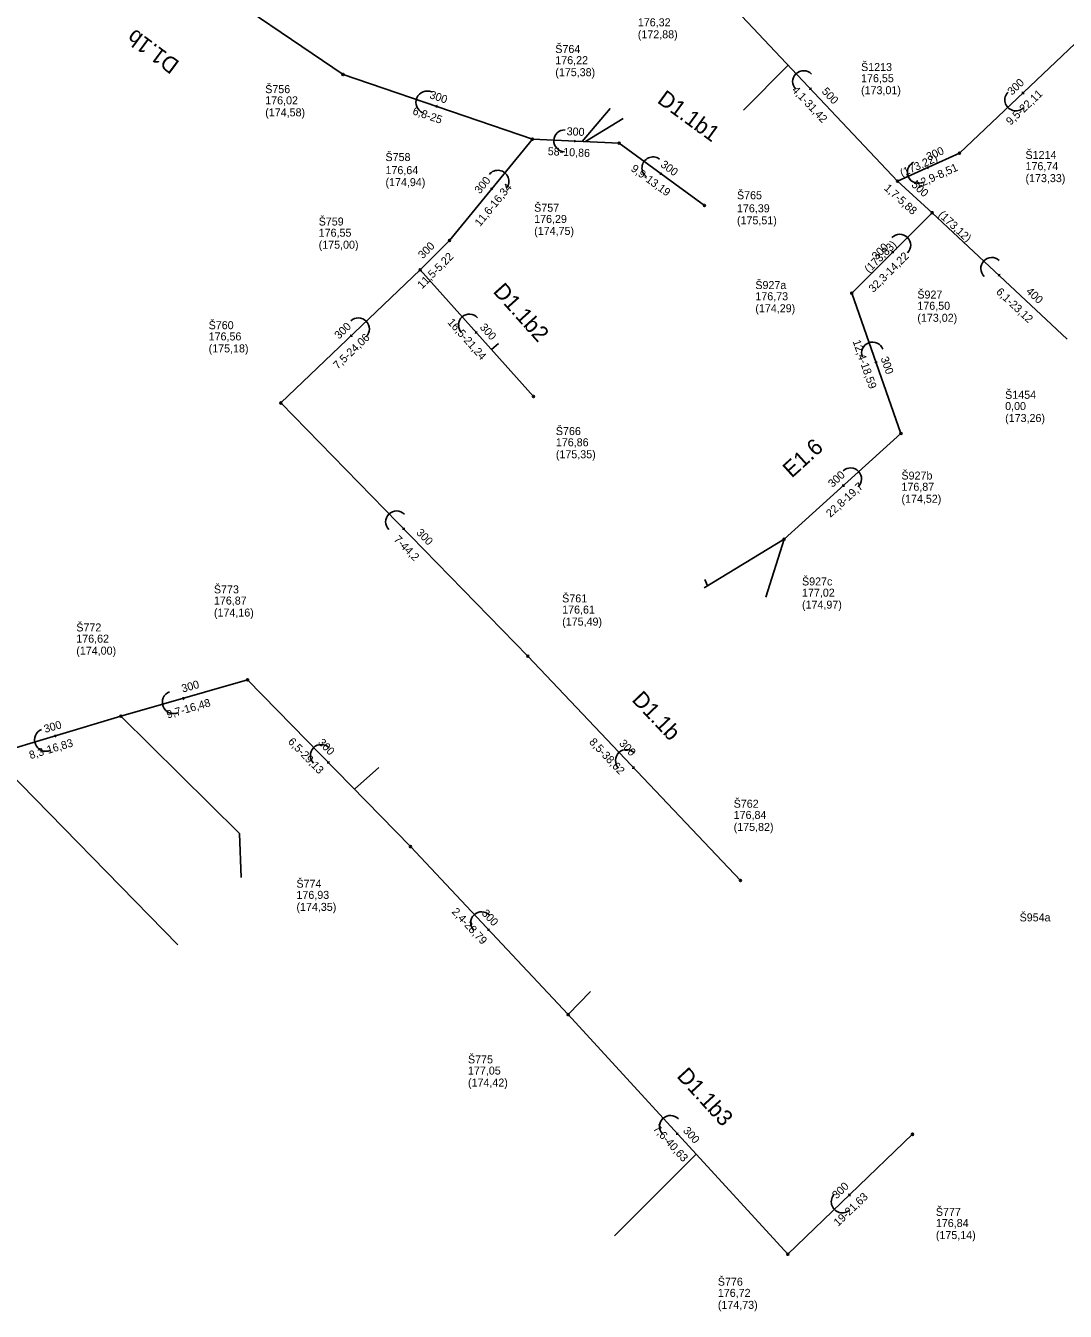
# Model space of a CAD drawing. Extents: x -548529 to -543591, y -1201432 to -1192608.
# Drawn here: x -544814 to -544684, y -1193635.3 to -1193474.6 of the extents above; entities that cross this region are included whole.
import ezdxf

# ---------------------------------------------------------------- set-up
doc = ezdxf.new("R2010")
doc.units = 0
for name, color, linetype in [('C3D_Bod-Značky', 7, 'Continuous'), ('C3D_Koridor', 7, 'Continuous'), ('C3D_Křižovatka', 7, 'Continuous'), ('C3D_Netisknutelná', 7, 'Continuous'), ('C3D_PP-zobrazeni v PR', 7, 'Continuous'), ('C3D_PR-Popisek', 7, 'Continuous'), ('C3D_SPR-Popisek', 7, 'Continuous'), ('C3D_Tlakove_potrubi_Popis', 7, 'Continuous'), ('C3D_ZPR-Formaty', 7, 'Continuous')]:
    doc.layers.add(name, color=color, linetype=linetype)

# ---------------------------------------------------------------- blocks, each defined once
blk = doc.blocks.new('100')
at = {"layer": 'Defpoints'}
blk.add_circle((0, 0), 0.127, dxfattribs=at)
blk = doc.blocks.new('91')
at = {"layer": 'Defpoints'}
blk.add_lwpolyline([(0.08, 0.14), (0.19, 0), (0.08, -0.14)], dxfattribs=at)
blk.add_arc((1.37, 0), 1.37, 270, 90, dxfattribs=at)
blk = doc.blocks.new('86')
at = {"layer": 'Defpoints'}
blk.add_lwpolyline([(0.08, 0.14), (0.19, 0), (0.08, -0.14)], dxfattribs=at)
blk.add_arc((1.37, 0), 1.37, 270, 90, dxfattribs=at)

msp = doc.modelspace()

# ---------------------------------------------------------------- linework, layer by layer
at = {"layer": 'C3D_Bod-Značky'}
for points in [[(-544774.31, -1193480.71), (-544792.51, -1193468.335), (-544810.71, -1193455.96)], [(-544705.03, -1193494.03), (-544726.568, -1193471.155)], [(-544681.22, -1193475.33), (-544697.27, -1193490.54)], [(-544750.65, -1193488.79), (-544774.31, -1193480.71)], [(-544760.99, -1193501.44), (-544750.65, -1193488.79)], [(-544739.8, -1193489.3), (-544750.65, -1193488.79)], [(-544729.145, -1193497.07), (-544739.8, -1193489.3)], [(-544697.27, -1193490.54), (-544705.03, -1193494.03)], [(-544700.674, -1193497.981), (-544705.03, -1193494.03)], [(-544710.739, -1193508.032), (-544700.674, -1193497.981)], [(-544683.794, -1193513.78), (-544700.674, -1193497.981)], [(-544764.68, -1193505.13), (-544760.99, -1193501.44)], [(-544782.07, -1193521.76), (-544764.68, -1193505.13)], [(-544750.51, -1193520.95), (-544764.68, -1193505.13)], [(-544704.58, -1193525.57), (-544710.739, -1193508.032)], [(-544751.22, -1193553.41), (-544782.07, -1193521.76)], [(-544719.18, -1193538.79), (-544704.58, -1193525.57)], [(-544724.65, -1193581.44), (-544751.22, -1193553.41)], [(-544786.23, -1193556.36), (-544802.07, -1193560.9)], [(-544765.878, -1193577.201), (-544786.23, -1193556.36)], [(-544802.07, -1193560.9), (-544818.19, -1193565.74)], [(-544746.181, -1193598.197), (-544765.878, -1193577.201)], [(-544718.728, -1193628.149), (-544746.181, -1193598.197)], [(-544703.141, -1193613.154), (-544718.728, -1193628.149)]]:
    msp.add_lwpolyline(points, dxfattribs=at)
at = {"layer": 'C3D_Koridor'}
for points in [[(-544718.694, -1193479.522), (-544724.269, -1193485.159)], [(-544744.415, -1193489.083), (-544740.938, -1193484.975)], [(-544744.005, -1193489.102), (-544739.285, -1193486.22)], [(-544755.759, -1193515.09), (-544754.866, -1193514.326)], [(-544719.18, -1193538.79), (-544729.157, -1193544.869)], [(-544719.18, -1193538.79), (-544721.481, -1193546.024)], [(-544728.744, -1193544.606), (-544729.096, -1193543.833)], [(-544802.07, -1193560.9), (-544787.248, -1193575.568), (-544787.049, -1193581.052)], [(-544818.19, -1193565.74), (-544794.95, -1193589.492)], [(-544772.88, -1193570.03), (-544769.826, -1193567.304)], [(-544746.181, -1193598.197), (-544743.389, -1193595.317)], [(-544730.184, -1193615.651), (-544740.37, -1193625.847)]]:
    msp.add_lwpolyline(points, dxfattribs=at)

# ---------------------------------------------------------------- block references
at = {"layer": 'C3D_PP-zobrazeni v PR'}
for p, xscale, yscale, rotation in [((-544774.31, -1193480.71), 1.0138865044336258, 1.0138865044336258, 152.43468640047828), ((-544750.65, -1193488.79), 0.9999999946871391, 0.9999999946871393, -73.99999975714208), ((-544739.8, -1193489.3), 1.0316957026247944, 1.0316957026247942, 156.4154111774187), ((-544697.27, -1193490.54), 0.9999999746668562, 0.999999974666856, -145.99999954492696), ((-544705.03, -1193494.03), 1.0000000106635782, 1.0000000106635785, 135.99999834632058), ((-544729.145, -1193497.07), 1.000000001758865, 1.000000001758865, -35.99999933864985), ((-544700.674, -1193497.981), 1.00000001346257, 1.0000000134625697, -178.0000000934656), ((-544760.99, -1193501.44), 1.0000000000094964, 1.0000000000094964, -132.0000013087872), ((-544764.68, -1193505.13), 1.000000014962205, 1.0000000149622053, 89.0000000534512), ((-544710.739, -1193508.032), 1.0000000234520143, 1.0000000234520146, 78.0000006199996), ((-544750.51, -1193520.95), 1.0000000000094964, 1.0000000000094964, -47.99999869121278), ((-544782.07, -1193521.76), 1.000000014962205, 1.0000000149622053, 89.0000000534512), ((-544704.58, -1193525.57), 1.0000000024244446, 1.0000000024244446, -104.00000032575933), ((-544719.18, -1193538.79), 1.00000000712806, 1.00000000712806, 43.0000005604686), ((-544751.22, -1193553.41), 1.0000000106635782, 1.0000000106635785, 134.00000165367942), ((-544786.23, -1193556.36), 1.0009848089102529, 1.000984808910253, 165.77567372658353), ((-544802.07, -1193560.9), 1.035124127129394, 1.0351241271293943, -157.49634583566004), ((-544765.878, -1193577.201), 1.0000000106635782, 1.0000000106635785, 134.00000165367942), ((-544724.65, -1193581.44), 1.0000000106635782, 1.0000000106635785, -45.99999834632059), ((-544746.181, -1193598.197), 1.00000000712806, 1.00000000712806, 133.00000056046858), ((-544703.141, -1193613.154), 1.0000000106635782, 1.0000000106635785, 44.00000165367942), ((-544718.728, -1193628.149), 1.000000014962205, 1.0000000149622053, 179.0000000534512)]:
    msp.add_blockref('100', p, dxfattribs=dict(at, xscale=xscale, yscale=yscale, rotation=rotation))
at = {"layer": 'C3D_SPR-Popisek'}
for name, p, xscale, yscale, rotation in [('91', (-544715.799, -1193482.592), 1.0000000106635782, 1.0000000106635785, 134.00000165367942), ('91', (-544762.48, -1193484.75), 1.033506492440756, 1.033506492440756, 156.95871826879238), ('91', (-544689.245, -1193482.935), 1.0000000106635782, 1.0000000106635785, -135.99999834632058), ('91', (-544745.225, -1193489.045), 1.00000001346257, 1.0000000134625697, 178.0000000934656), ('91', (-544734.472, -1193493.185), 1.000000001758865, 1.000000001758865, 144.00000066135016), ('91', (-544755.82, -1193495.115), 1.000000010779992, 1.0000000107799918, 51.00000108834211), ('91', (-544701.15, -1193492.285), 1.0169562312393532, 1.016956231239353, -153.02398354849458), ('91', (-544705.706, -1193503.006), 0.999999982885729, 0.9999999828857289, 45), ('91', (-544692.234, -1193505.88), 1.00000000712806, 1.00000000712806, 136.99999943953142), ('86', (-544757.595, -1193513.04), 1.0000000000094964, 1.0000000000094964, 132.0000013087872), ('86', (-544773.375, -1193513.445), 1.0000000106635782, 1.0000000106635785, 44.00000165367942), ('91', (-544707.66, -1193516.801), 0.9999999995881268, 0.9999999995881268, 110.00000065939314), ('91', (-544711.88, -1193532.18), 1.00000000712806, 1.00000000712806, 43.0000005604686), ('86', (-544766.645, -1193537.585), 0.999999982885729, 0.9999999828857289, 135), ('86', (-544794.15, -1193558.63), 1.0365458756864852, 1.0365458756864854, -158.02850914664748), ('86', (-544810.13, -1193563.32), 1.035124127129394, 1.0351241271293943, -157.49634583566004), ('86', (-544776.054, -1193566.78), 0.999999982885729, 0.9999999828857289, 135), ('86', (-544737.935, -1193567.425), 1.0000000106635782, 1.0000000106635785, 134.00000165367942), ('86', (-544756.03, -1193587.699), 1.0000000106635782, 1.0000000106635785, 134.00000165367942), ('86', (-544732.454, -1193613.173), 1.00000000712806, 1.00000000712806, 133.00000056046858), ('86', (-544710.934, -1193620.652), 1.0000000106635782, 1.0000000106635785, -135.99999834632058)]:
    msp.add_blockref(name, p, dxfattribs=dict(at, xscale=xscale, yscale=yscale, rotation=rotation))

# ---------------------------------------------------------------- texts
at = {"layer": 'C3D_Křižovatka'}
for s, p in [('Š764', (-544747.78, -1193478.02)), ('Š1213', (-544709.57, -1193480.27)), ('Š756', (-544784.03, -1193483.04)), ('Š758', (-544769, -1193491.53)), ('Š1214', (-544689.02, -1193491.26)), ('Š765', (-544725.075, -1193496.3)), ('Š757', (-544750.42, -1193497.86)), ('Š759', (-544777.35, -1193499.58)), ('Š927a', (-544722.779, -1193507.522)), ('Š927', (-544702.534, -1193508.711)), ('Š760', (-544791.1, -1193512.54)), ('Š1454', (-544691.564, -1193521.24)), ('Š766', (-544747.71, -1193525.77)), ('Š927b', (-544704.52, -1193531.33)), ('Š927c', (-544716.95, -1193544.56)), ('Š773', (-544790.44, -1193545.55)), ('Š761', (-544746.92, -1193546.68)), ('Š772', (-544807.64, -1193550.31)), ('Š762', (-544725.49, -1193572.34)), ('Š774', (-544780.128, -1193582.331)), ('Š954a', (-544689.755, -1193586.547)), ('Š775', (-544758.691, -1193604.287)), ('Š777', (-544700.221, -1193623.344)), ('Š776', (-544727.468, -1193632.069))]:
    msp.add_text(s, height=1, dxfattribs=at).set_placement(p)
at = {"layer": 'C3D_Netisknutelná'}
for s, rotation, p in [('D1.1b', 143.46, (-544794.62, -1193479.169)), ('D1.1b1', 323.9, (-544735.16, -1193484.145)), ('D1.1b2', 311.85, (-544755.655, -1193507.874)), ('E1.6', 42.16, (-544718.233, -1193531.212)), ('D1.1b', 313.47, (-544738.319, -1193558.931)), ('D1.1b3', 312.51, (-544732.698, -1193605.946))]:
    msp.add_text(s, height=2, rotation=rotation, dxfattribs=at).set_placement(p)
at = {"layer": 'C3D_PR-Popisek'}
for s, rotation, p in [('300', 341.14, (-544763.579, -1193483.638)), ('500', 313.28, (-544714.556, -1193482.889)), ('300', 43.46, (-544690.714, -1193483.369)), ('300', 357.31, (-544746.378, -1193488.29)), ('300', 24.22, (-544701.135, -1193491.504)), ('300', 323.9, (-544734.712, -1193492.151)), ('300', 50.74, (-544757.207, -1193495.699)), ('500', 317.79, (-544703.353, -1193494.603)), ('300', 45, (-544764.345, -1193503.812)), ('300', 44.96, (-544707.639, -1193503.953)), ('400', 316.89, (-544689.028, -1193507.918)), ('300', 43.72, (-544774.815, -1193513.85)), ('300', 311.85, (-544757.286, -1193512.342)), ('300', 289.35, (-544707.142, -1193516.163)), ('300', 42.16, (-544713.144, -1193532.377)), ('300', 314.27, (-544765.228, -1193538.034)), ('300', 15.99, (-544794.334, -1193557.955)), ('300', 16.71, (-544811.522, -1193563.008)), ('300', 314.32, (-544777.517, -1193564.277)), ('300', 313.47, (-544739.874, -1193564.369)), ('300', 313.17, (-544757.053, -1193585.593)), ('300', 312.51, (-544731.886, -1193612.754)), ('300', 43.89, (-544712.612, -1193621.291))]:
    msp.add_text(s, height=1, rotation=rotation, dxfattribs=at).set_placement(p)
at = {"layer": 'C3D_Tlakove_potrubi_Popis'}
for s, p in [('176,32 ', (-544737.468, -1193474.685)), ('(172,88)', (-544737.468, -1193476.185)), ('176,22 ', (-544747.78, -1193479.42)), ('(175,38)', (-544747.78, -1193480.92)), ('176,55 ', (-544709.57, -1193481.67)), ('(173,01)', (-544709.57, -1193483.17)), ('176,02 ', (-544784.03, -1193484.44)), ('(174,58)', (-544784.03, -1193485.94)), ('176,64 ', (-544769, -1193493.16)), ('176,74 ', (-544689.02, -1193492.66)), ('(174,94)', (-544769, -1193494.66)), ('(173,33)', (-544689.02, -1193494.16)), ('176,39 ', (-544725.075, -1193497.93)), ('176,29 ', (-544750.42, -1193499.26)), ('(175,51)', (-544725.075, -1193499.43)), ('176,55 ', (-544777.35, -1193500.98)), ('(174,75)', (-544750.42, -1193500.76)), ('(175,00)', (-544777.35, -1193502.48)), ('176,73 ', (-544722.779, -1193508.922)), ('(174,29)', (-544722.779, -1193510.422)), ('176,50 ', (-544702.534, -1193510.111)), ('(173,02)', (-544702.534, -1193511.611)), ('176,56 ', (-544791.1, -1193513.94)), ('(175,18)', (-544791.1, -1193515.44)), ('0,00 ', (-544691.564, -1193522.64)), ('(173,26)', (-544691.564, -1193524.14)), ('176,86 ', (-544747.71, -1193527.17)), ('(175,35)', (-544747.71, -1193528.67)), ('176,87 ', (-544704.52, -1193532.73)), ('(174,52)', (-544704.52, -1193534.23)), ('177,02 ', (-544716.95, -1193545.96)), ('176,87 ', (-544790.44, -1193546.95)), ('(174,97)', (-544716.95, -1193547.46)), ('(174,16)', (-544790.44, -1193548.45)), ('(175,49)', (-544746.92, -1193549.58)), ('176,61 ', (-544746.92, -1193548.08)), ('176,62 ', (-544807.64, -1193551.71)), ('(174,00)', (-544807.64, -1193553.21)), ('176,84 ', (-544725.49, -1193573.74)), ('(175,82)', (-544725.49, -1193575.24)), ('176,93 ', (-544780.128, -1193583.731)), ('(174,35)', (-544780.128, -1193585.231)), ('177,05 ', (-544758.691, -1193605.687)), ('(174,42)', (-544758.691, -1193607.187)), ('176,84 ', (-544700.221, -1193624.744)), ('(175,14)', (-544700.221, -1193626.244)), ('176,72 ', (-544727.468, -1193633.469)), ('(174,73)', (-544727.468, -1193634.969))]:
    msp.add_text(s, height=1, dxfattribs=at).set_placement(p)
at = {"layer": 'C3D_ZPR-Formaty'}
for s, rotation, p in [('4,1-31,42', 313.28, (-544718.286, -1193482.723)), ('9,5-22,11', 43.46, (-544690.891, -1193487.113)), ('6,8-25', 341.14, (-544765.699, -1193485.657)), ('58-10,86', 357.31, (-544748.741, -1193490.783)), ('  (173,22)   ', 24.22, (-544705.112, -1193493.848)), ('9,9-13,19', 323.9, (-544738.418, -1193492.661)), ('12,9-8,51', 24.22, (-544702.523, -1193494.989)), ('11,6-16,34', 50.74, (-544757.187, -1193499.784)), ('1,7-5,88', 317.79, (-544706.77, -1193495.018)), ('  (173,12)   ', 316.89, (-544700.537, -1193497.835)), ('  (173,83)   ', 44.96, (-544709.094, -1193506.107)), ('11,5-5,22', 45, (-544764.424, -1193507.551)), ('32,3-14,22', 44.96, (-544708.038, -1193508.02)), ('6,1-23,12', 316.89, (-544692.776, -1193507.975)), ('16,5-21,24', 311.85, (-544761.32, -1193511.73)), ('7,5-24,06', 43.72, (-544774.969, -1193517.598)), ('12,4-18,59', 289.35, (-544710.636, -1193514.055)), ('22,8-19,7', 42.16, (-544713.396, -1193536.117)), ('7-44,2', 314.27, (-544768.033, -1193538.884)), ('9,7-16,48', 15.99, (-544796.214, -1193561.194)), ('8,3-16,83', 16.71, (-544813.366, -1193566.275)), ('6,5-29,13', 314.32, (-544781.265, -1193564.164)), ('8,5-38,62', 313.47, (-544743.617, -1193564.192)), ('2,4-28,79', 313.17, (-544760.791, -1193585.401)), ('7,6-40,63', 312.51, (-544735.632, -1193612.519)), ('19-21,63', 43.89, (-544712.422, -1193624.72))]:
    msp.add_text(s, height=1, rotation=rotation, dxfattribs=at).set_placement(p)

doc.saveas('drawing.dxf')
